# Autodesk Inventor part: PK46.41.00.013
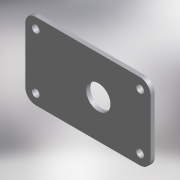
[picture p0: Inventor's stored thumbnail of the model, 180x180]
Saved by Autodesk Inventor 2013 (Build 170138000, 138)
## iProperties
Created: 2005-05
Part Number: PK46.41.00.013
Material: Steel, Mild
Description: Плита
Document SubType Name: Листовой материал
Designer: PVitaliy
Manufacturer: Standard
Standards Organization: Custom
Density: 7.86 g/cm^3
Mass: 861.359 g
Surface Area: 413.438 cm^2
Volume: 109.588 cm^3
Author: PVitaliy
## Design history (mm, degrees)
node "ПК46.41.00.011" dims "d0" = 10
  node "РабПлоскость1"
body "Solid1"
tag "TaggingFeature2"
feature "DerivedBody::ПК46.41.00.011" dims "d0" = 10
